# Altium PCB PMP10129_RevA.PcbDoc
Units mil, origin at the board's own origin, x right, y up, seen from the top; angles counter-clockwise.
Board outline 7300 x 1875 mil, 2 copper layers (Top Layer, Bottom Layer), stack 62 mil thick; 91 components, 49 nets, 201 pads, 18 vias.
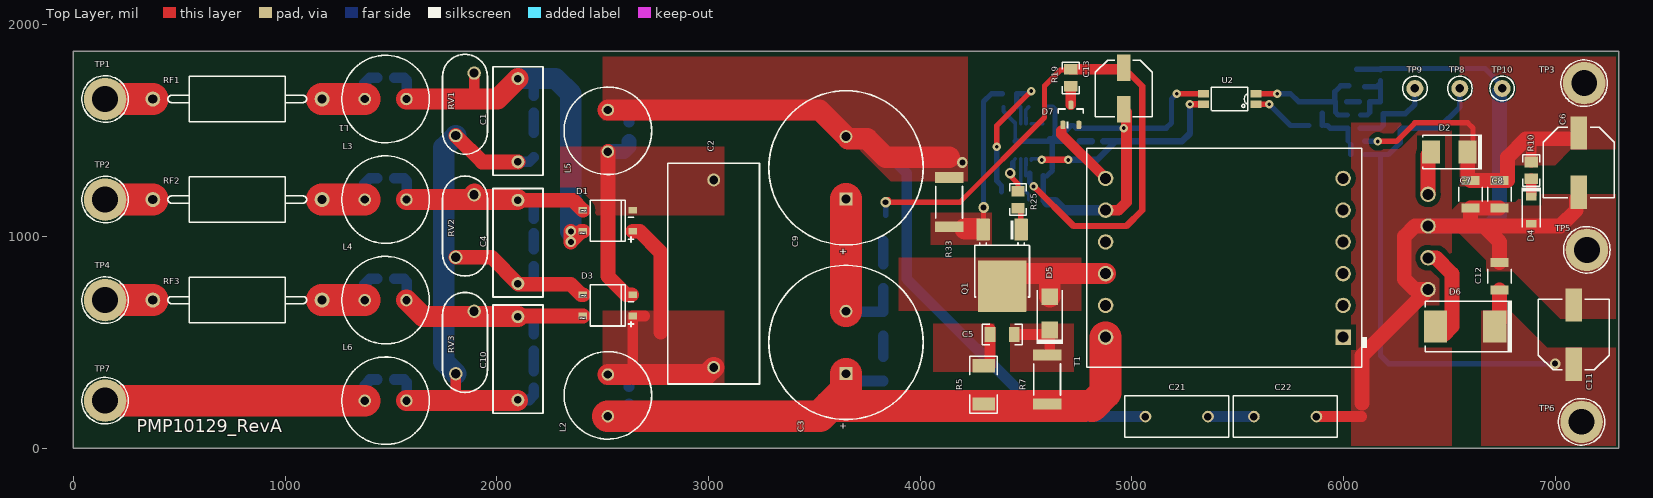
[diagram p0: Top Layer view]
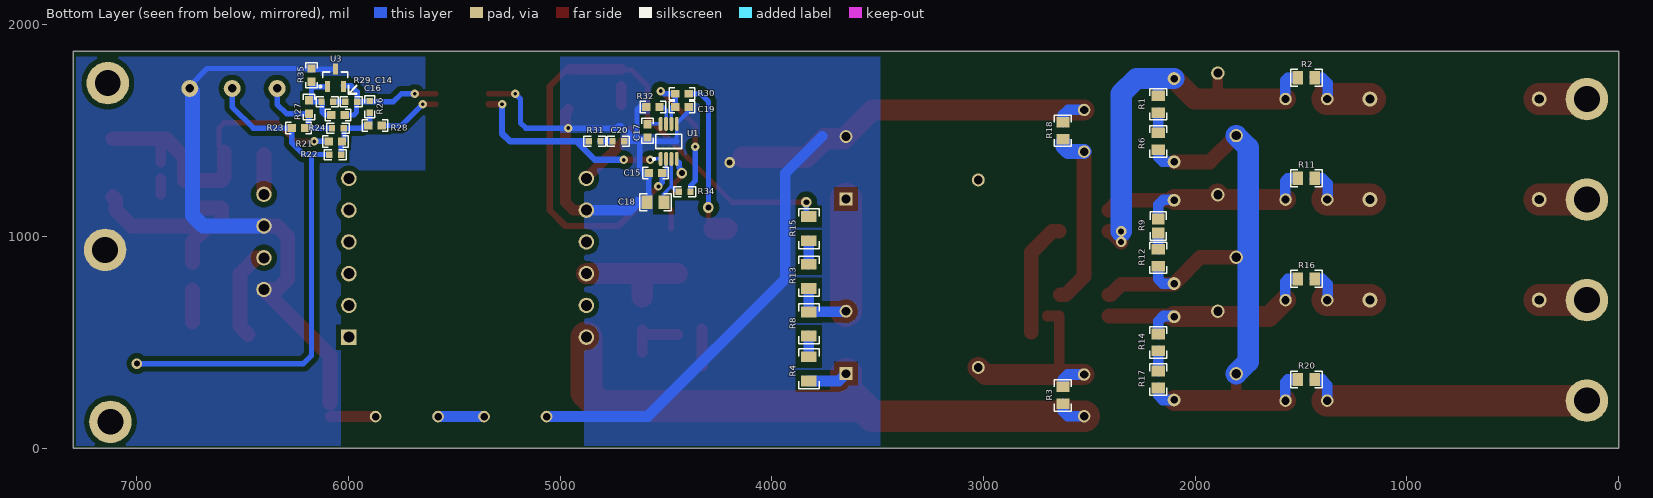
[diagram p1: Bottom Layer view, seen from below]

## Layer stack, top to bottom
Top Solder: solder mask 0.4, Solder Resist, Dk 3.5
Top Layer: signal copper 1.4
Dielectric1: core 59.2, FR-4, Dk 4.8
Bottom Layer: signal copper 1.4
Bottom Solder: solder mask 0.4, Solder Resist, Dk 3.5

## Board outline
0,0 7300,0 7300,1875 0,1875

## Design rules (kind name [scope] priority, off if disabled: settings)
AcuteAngle [All] p1: minimum=4.50000000000000E+0001 checktracksonly=FALSE
AssemblyTestPointUsage [All] p1: valid=2
Clearance Clearance_Keepouts [((IsTrack Or IsArc) And Not InPoly) And IsFree and IsKeepOut vs ((IsTrack Or IsArc) And Not InPoly) And IsFree and IsKeepOut] p1: gap=0
Clearance Clearance_BoardEdge_MountingHoles [OnCopper and InComponentClass('Mounting Holes') vs IsKeepOut] p2: gap=20
Clearance Clearance_BoardEdge_Poly [OnCopper and InPoly vs IsKeepOut] p3: gap=25
Clearance Clearance_BoardEdge [OnCopper and Not InComponentClass('Logo') and not InComponentClass('FiducialMark') and not InRegion(1000,500,4000,800) and Not IsKeepout vs IsKeepOut] p4: gap=20
Clearance Clearance_Poly [InPolygon] p5: gap=25
Clearance [All] p6: gap=7.87
ComponentClearance ComponentClearance_MountingHoles_FiducialMarks [InComponentClass('Mounting Holes') vs InComponentClass('FiducialMark')] p1: gap=50 collisioncheckmode=3 verticalgap=10 showdistances=FALSE
ComponentClearance ComponentClearance_Shunt [InComponentClass('Header') vs InComponentClass('Shunt')] p2: gap=0 collisioncheckmode=3 verticalgap=0 showdistances=FALSE
ComponentClearance ComponentClearance_Logo [InComponentClass('Logo')] p3: gap=50 collisioncheckmode=3 verticalgap=10 showdistances=FALSE
ComponentClearance ComponentClearance_ScrewToNut [(HasFootprint('NY PMS 440 0025 PH')) vs (HasFootprint('Keystone_1902C'))] p4: gap=5 collisioncheckmode=3 verticalgap=10 showdistances=FALSE
ComponentClearance ComponentClearance_MountingHoles [InComponentClass('Mounting Holes')] p5: gap=250 collisioncheckmode=3 verticalgap=100000 showdistances=FALSE
ComponentClearance ComponentClearance_SmallPassives [HasFootprint('0201*') or HasFootprint('0402*') or HasFootprint('0508') or HasFootprint('0603*') or HasFootprint('0612') or HasFootprint('0805*') or HasFootprint('0815*') or HasFootprint('0830*') or HasFootprint('1206*') or HasFootprint('1210*') or HasFootprint('1808*') or HasFootprint('1812*') or HasFootprint('1825*') or HasFootprint('2010*') or HasFootprint('2220*') or HasFootprint('2225*') or HasFootprint('2512*') or HasFootprint('2728*') or HasFootprint('3518*') vs HasFootprint('0201*') or HasFootprint('0402*') or HasFootprint('0508') or HasFootprint('0603*') or HasFootprint('0612') or HasFootprint('0805*') or HasFootprint('0815*') or HasFootprint('0830*') or HasFootprint('1206*') or HasFootprint('1210*') or HasFootprint('1808*') or HasFootprint('1812*') or HasFootprint('1825*') or HasFootprint('2010*') or HasFootprint('2220*') or HasFootprint('2225*') or HasFootprint('2512*') or HasFootprint('2728*') or HasFootprint('3518*')] p6: gap=20 collisioncheckmode=3 verticalgap=10 showdistances=FALSE
ComponentClearance ComponentClearance_THtoSMT [IsThruComponent vs IsSMTComponent] p7: gap=10 collisioncheckmode=3 verticalgap=10 showdistances=FALSE
ComponentClearance ComponentClearance_THtoTH [IsThruComponent vs IsThruComponent] p8: gap=20 collisioncheckmode=3 verticalgap=30 showdistances=FALSE
ComponentClearance [All] p9: gap=10 collisioncheckmode=3 verticalgap=10 showdistances=FALSE
DiffPairsRouting [All] p1: maxlimit=100 minlimit=10 mostfreqgap=10 toplayer_minwidth=15 toplayer_maxwidth=15 toplayer_prefwidth=15 bottomlayer_minwidth=15 bottomlayer_maxwidth=15 bottomlayer_prefwidth=15 maxuncoupledlength=1000
FabricationTestPointUsage TestPointUsage [All] p1: valid=2 allowmultiple=FALSE
FabricationTestpoint Testpoint [All] p1: side=3 testpointundercomponent=TRUE minsize=40 maxsize=100 preferedsize=60 minholesize=0 maxholesize=40 preferedholesize=32 testpointgrid=1 allowsidetop=TRUE allowsidebottom=TRUE usegrid=TRUE gridtolerance=0.01
FanoutControl Fanout_LCC [IsLCC] p1: bgadir=Out bgaviamode=Centered fanoutstyle=Auto fanoutdirection=Alternating viagrid=1 // Fanout_LCC (Default Rule)
FanoutControl Fanout_BGA [IsBGA] p2: bgadir=Out bgaviamode=Centered fanoutstyle=Auto fanoutdirection=Alternating viagrid=1 // Fanout_BGA (Default Rule)
FanoutControl Fanout_Default [All] p4: bgadir=Out bgaviamode=Centered fanoutstyle=Auto fanoutdirection=Alternating viagrid=1 // Fanout_Default (Default Rule)
FanoutControl Fanout_Small [(CompPinCount < 5)] p5: bgadir=Out bgaviamode=Centered fanoutstyle=Auto fanoutdirection=OutThenIn viagrid=1 // Fanout_Small (Default Rule)
Height [All] p1: minheight=0 maxheight=3000 prefheight=500
HoleSize [All] p1: absolutevalues=TRUE maxlimit=251 minlimit=8 maxpercent=80.000 minpercent=20.000
MinimumAnnularRing MinimumAnnularRing_ThermalPadVias [IsVia and InAnyComponent] p1: minimumring=5.91
MinimumAnnularRing [All] p2: minimumring=9
MinimumSolderMaskSliver MinimumSolderMaskSliver_Logo [InComponentClass('Logo') vs InComponentClass('Logo')] p1: minsoldermaskwidth=0.7
MinimumSolderMaskSliver [All] p2: minsoldermaskwidth=3.94
PlaneConnect [All] p1: planeconnectstyle=Relief reliefexpansion=10 reliefentries=4 reliefconductorwidth=10 reliefairgap=10
PolygonConnect [All] p1: connectstyle=Direct reliefconductorwidth=10 reliefentries=4 polygonreliefangle="90 Angle" airgapwidth=10
RoutingVias ThermalPadVias [IsVia and InAnyComponent] p1: holewidth=7.87 width=19.68 viastyle="Through Hole" minholewidth=7.87 minwidth=19.68 maxholewidth=12.99 maxwidth=23.62
RoutingVias [All] p2: holewidth=16 width=34 viastyle="Through Hole" minholewidth=7.87 minwidth=26 maxholewidth=40 maxwidth=65
SilkToBoardRegionClearance [Not ((IsComment or IsDesignator) And (Hide <> 'False')) and not InRegion(1000,500,4000,800)] p1:
SilkToSilkClearance SilkToSilkClearance_Pb-FreeLogo [(HasFootprint('Pb-Free_Overlay_Medium') OR HasFootprint('Pb-Free_Overlay_Small')) vs (HasFootprint('Pb-Free_Overlay_Medium') OR HasFootprint('Pb-Free_Overlay_Small'))] p1 off: silktosilkclearance=0
SilkToSilkClearance [All] p2 off: silktosilkclearance=5
SilkToSolderMaskClearance "Silk to Solder Mask Opening" [All] p1 off: minsilkscreentomaskgap=1 clearancetoexposedcopper=FALSE
SolderMaskExpansion [All] p1: expansion=1.97
UnpouredPolygon [All] p1: allowunpoured=FALSE
Width [All] p1: maxlimit=150 minlimit=6 preferedwidth=10 minimp=50.000000 maximp=50.000000 favimp=50.000000 checkconnectedcopper=TRUE
13 further rules are at their usual default settings.

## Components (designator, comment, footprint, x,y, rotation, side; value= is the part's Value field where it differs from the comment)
C1 "B32921C3104M" B32921_1300x1200x600 2100,1550 r270 top
C2 "B32653A224J" B32653_2650x2050x1100 3025,825 r90 top
C3 "EKXG401ELL680MM25S" KXG_1800x3150 3650,500 r90 top
C4 "B32921C3104M" B32921_1300x1200x600 2100,975 r270 top
C5 "C3216C0G2J152J" 1206 4387.5,537.5 r0 top
C6 "EEE-FK1H101P" SM_RADIAL_F 7112.5,1350 r270 top
C7 "C3225X7R1H106M250AC" 1210_280 6600,1200 r270 top
C8 "C3225X7R1H106M250AC" 1210_280 6737.5,1200 r270 top
C9 "EKXG401ELL680MM25S" KXG_1800x3150 3650,1325 r90 top
C10 "B32921C3104M" B32921_1300x1200x600 2100,425 r270 top
C11 "EEE-FK1A471P" SM_RADIAL_F 7087.5,537.5 r90 top
C12 "C3225X7R1C226K250AC" 1210_280 6737.5,812.5 r90 top
C13 "EEE-FC1H100P" SM_RADIAL_D 4962.5,1700 r270 top
C14 "Used in BOM report" 0603_HV 5987.5,1637.5 r180 bottom
C15 "C1608X7R1H104K" 0603 4550,1300 r0 bottom
C16 "C0603C103J5RACTU" 0603 6050,1575 r180 bottom
C17 "C1608X7R1H473K" 0603 4587.5,1500 r270 bottom
C18 "08055C105KAT2A" 0805_HV 4550,1162.5 r0 bottom
C19 "GRM1885C1H561JA01D" 0603 4425,1612.5 r180 bottom
C20 "Used in BOM report" 0603_HV 4725,1450 r180 bottom
C21 "VY2472M49Y5US63V7" VY2_1250x500x1650 5212.5,150 r0 top
C22 "VY2472M49Y5US63V7" VY2_1250x500x1650 5725,150 r0 top
D1 "MB8S-TP" MBS-1 2525,1075 r180 top
D2 "MURS140-13-F" SMB 6500,1400 r180 top
D3 "MB8S-TP" MBS-1 2525,675 r180 top
D4 "MMSZ5255B-7-F" SOD-123 6887.5,1125 r270 top
D5 "US1K-13-F" SMA 4612.5,637.5 r90 top
D6 "MBRS3100T3G" SMC 6575,575 r180 top
D7 "BAS21-7-F" SOT-23 4712.5,1575 r90 top
L1 "7447480102" WE_TI_1014 1475,1650 r0 top
L2 "7447480102" WE_TI_1014 2525,250 r270 top
L3 "7447480102" WE_TI_1014 1475,1175 r0 top
L4 "7447480102" WE_TI_1014 1475,700 r0 top
L5 "7447480102" WE_TI_1014 2525,1500 r90 top
L6 "7447480102" WE_TI_1014 1475,225 r0 top
Q1 "IPD90R1K2C3" DPAK 4387.5,900 r270 top
R1 "Used in BOM report" 0805_HV 2175,1625 r90 bottom
R2 "CRCW080510K0FKEA" 0805_HV 1475,1750 r0 bottom
R3 "CRCW080510K0FKEA" 0805_HV 2625,250 r270 bottom
R4 "CRCW1206499KFKEA" 1206 3825,375 r270 bottom
R5 "CRCW2010150RJNEF" 2010 4300,300 r270 top
R6 "Used in BOM report" 0805_HV 2175,1450 r90 bottom
R7 "CRCW251247K0JNEG" 2512 4600,325 r270 top
R8 "CRCW1206499KFKEA" 1206 3825,587.5 r270 bottom
R9 "Used in BOM report" 0805 2175,1050 r90 bottom
R10 "CRCW08050000Z0EAHP" 0805_HV 6887.5,1312.5 r90 top
R11 "CRCW080510K0FKEA" 0805_HV 1475,1275 r0 bottom
R12 "Used in BOM report" 0805_HV 2175,900 r90 bottom
R13 "CRCW1206499KFKEA" 1206 3825,812.5 r270 bottom
R14 "Used in BOM report" 0805_HV 2175,500 r90 bottom
R15 "CRCW1206499KFKEA" 1206 3825,1037.5 r270 bottom
R16 "CRCW080510K0FKEA" 0805_HV 1475,800 r0 bottom
R17 "Used in BOM report" 0805_HV 2175,325 r90 bottom
R18 "CRCW080510K0FKEA" 0805_HV 2625,1500 r90 bottom
R19 "CRCW080510R0FKEA" 0805_HV 4712.5,1750 r270 top
R20 "CRCW080510K0FKEA" 0805_HV 1475,325 r0 bottom
R21 "CRCW06030000Z0EA" 0603 6062.5,1450 r0 bottom
R22 "Used in BOM report" 0603_HV 6062.5,1387.5 r0 bottom
R23 "CRCW060349R9FKEA" 0603 6237.5,1512.5 r0 bottom
R24 "Used in BOM report" 0603_HV 6050,1512.5 r0 bottom
R25 "CRCW08050000Z0EA" 0805_HV 4462.5,1175 r270 top
R26 "Used in BOM report" 0603_HV 5900,1612.5 r270 bottom
R27 "CRCW060320K0FKEA" 0603 6187.5,1612.5 r270 bottom
R28 "CRCW06032K00JNEA" 0603 5875,1525 r0 bottom
R29 "Used in BOM report" 0603_HV 6100,1637.5 r0 bottom
R30 "RT0603DRE07499RL" 0603 4425,1675 r180 bottom
R31 "Used in BOM report" 0603_HV 4837.5,1450 r0 bottom
R32 "CRCW060360K4FKEA" 0603 4562.5,1612.5 r180 bottom
R33 "ERJ-1TRQFR62U" 2512 4137.5,1162.5 r270 top
R34 "Used in BOM report" 0603_HV 4412.5,1212.5 r0 bottom
R35 "CRCW06035K23FKEA" 0603 6175,1762.5 r270 bottom
RF1 "FW20A10R0JACT-ND" RES_PWR4522 775,1650 r180 top
RF2 "FW20A10R0JACT-ND" RES_PWR4522 775,1175 r180 top
RF3 "FW20A10R0JACT-ND" RES_PWR4522 775,700 r180 top
RV1 "S10K275E2" VAR_S10K275E2 1850,1625 r90 top
RV2 "S10K275E2" VAR_S10K275E2 1850,1050 r90 top
RV3 "S10K275E2" VAR_S10K275E2 1850,500 r90 top
T1 "750315315" Wurth_750315315 5437.5,900 r180 top
TP1 "Suggest using a net name here" Keystone1503-2 150,1650 r270 top
TP2 "Suggest using a net name here" Keystone1503-2 150,1175 r270 top
TP3 "Suggest using a net name here" Keystone1503-2 7137.5,1725 r0 top
TP4 "Suggest using a net name here" Keystone1503-2 150,700 r270 top
TP5 "Suggest using a net name here" Keystone1503-2 7150,937.5 r0 top
TP6 "Suggest using a net name here" Keystone1503-2 7125,125 r0 top
TP7 "Suggest using a net name here" Keystone1503-2 150,225 r270 top
TP8 "5000" Keystone5000 6550,1700 r0 top
TP9 "5000" Keystone5000 6337.5,1700 r0 top
TP10 "5001" Keystone5001 6750,1700 r0 top
U1 "LM5021MM-1/NOPB" MUA08A_N 4487.5,1450 r90 bottom
U2 "TCMT1107" SOP-4 5462.5,1650 r180 top
U3 "LMV431AIMF/NOPB" MF03A_N 6062.5,1750 r90 bottom

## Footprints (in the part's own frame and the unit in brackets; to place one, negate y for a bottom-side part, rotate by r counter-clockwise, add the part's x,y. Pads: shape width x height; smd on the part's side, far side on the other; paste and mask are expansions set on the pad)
0603 [mm] "0603 from SM-752 data"
  rect 1x0.95 smd: 1(-0.8,0) 2(0.8,0)
  silkscreen extent -1.52,-0.69 1.52,0.69, body extent -0.87,-0.47 0.87,0.47, height 0.85
0603_HV [mil] "Ernesto recommended land pattern.  26 mil between pads."
  rect 30x30 smd: 1(-28,0) 2(28,0)
  silkscreen extent -52,-24 52,24, body extent -34,-19 34,19, height 33
0805 [mm] "0805 from SM-752 data"
  rect 1.3x1.5 smd: 1(-0.85,0) 2(0.85,0)
  silkscreen extent -1.72,-0.97 1.72,0.97, body extent -1.1,-0.72 1.1,0.72, height 1.1
0805_HV [mil] "0805 with 30mil clearance between pads"
  rect 50x63 smd: 1(-40,0) 2(40,0)
  silkscreen extent -74,-40 74,40, body extent -43,-29 43,29, height 57
1206 [mm] "1206 from SM-752 data"
  rect 1.3x1.85 smd: 1(-1.45,0) 2(1.45,0)
  silkscreen extent -2.4,-1.21 2.4,1.21, body extent -1.7,-0.9 1.7,0.9, height 1.35
1210_280 [mm] "SMD, 2-Leads, Body 3.6x2.8mm, Height 2.8mm"
  rect 1.1x2.2 smd: 1(-1.65,0) 2(1.65,0)
  silkscreen extent -0.84,-1.4 0.84,1.4, body extent -1.8,-1.4 1.8,1.4, height 2.8
2010 [mm] "Chip Capacitor, Body 5.08x2.54mm, IPC Medium Density"
  rect 1.6x2.7 smd: 1(-2.3,0) 2(2.3,0)
  silkscreen extent -3.42,-1.65 3.42,1.65, body extent -2.73,-1.45 2.73,1.45, height 1.66
2512 [mm] "Chip Resistor, Body 6.3x3.2mm, IPC Medium Density"
  rect 1.3x3.4 smd: 1(-2.95,0) 2(2.95,0)
  silkscreen extent -1.9,-1.6 1.9,1.6, body extent -3.22,-1.67 3.22,1.67, height 0.71
B32653_2650x2050x1100 [mm] "TH, 2-Leads, Body 26.5x11mm, Pin Spacing 22.5mm"
  round 1.55 hole 1.05: 1(-11.25,0) 2(11.25,0)
  silkscreen extent -13.25,-5.5 13.25,5.5, body extent -13.25,-5.5 13.25,5.5, height 20.5
B32921_1300x1200x600 [mm] "EPCOS"
  round 1.55 hole 0.9: 1(-5,0) 2(5,0)
  silkscreen extent -6.4,-3 6.6,3, body extent -6.4,-3 6.6,3, height 12
DPAK [mm] "D-PAK, 3-Pads, Body 6.22x6.73mm (max), TO-252AA using nominal STEP model"
  rrect6% 2.6x1.6 smd: 1(-3.4,2.28) 3(-3.4,-2.28)
  rrect2% 6.2x5.8 smd paste-2.9: 4(3.4,0)
  silkscreen extent -4.5,-3.3 4.7,3.28, body extent -3.86,-3.29 5.84,3.29, height 2.48
Keystone1503-2 [mm] "Double Turret"
  round 5.1 hole 3.1: 1(0,0)
  silkscreen extent -2.79,-2.79 2.79,2.79, body extent -2.4,-2.4 2.38,2.4, height 9.22
Keystone5000 [mil] "For Keystone 500x miniature loop terminals"
  round 80 hole 40: 1(0,0)
  silkscreen extent -58,-58 58,58, body extent -49,-49 49,49, height 182
Keystone5001 [mil] "For Keystone 500x miniature loop terminals"
  round 80 hole 40: 1(0,0)
  silkscreen extent -58,-58 58,58, body extent -49,-49 49,49, height 182
KXG_1800x3150 [mm] "TH, 2-Leads, Dia 18mm, Pin Spacing 7.5mm"
  rect 1.55x1.55 hole 1.05: 1(-3.75,0)
  round 1.55 hole 1.05: 2(3.75,0)
  silkscreen extent -9.25,-9.25 9.25,9.25, body extent -9.18,-9.33 9.22,9.14, height 33.01
MBS-1 [mm] "SOP, 4-Leads, Body 4.95x4.2mm"
  rect 1x0.8 smd: 1(-3,1.27) 2(3,1.27) 3(3,-1.27) 4(-3,-1.27)
  silkscreen extent -3.08,-2.48 2.1,2.56, body extent -3.45,-2.47 3.45,2.48, height 2.9
MF03A_N [mm] "SOT23, 3-Leads, Body 2.9x1.3mm, Pitch 0.95mm, Lead Span 2.4mm, IPC Medium Density"
  rect 1.3x0.6 smd: 1(-1.05,0.95) 2(-1.05,-0.95) 3(1.05,0)
  silkscreen extent -1.17,-1.5 0.7,1.93, body extent -0.7,-1.5 0.7,1.5, height 1.12
MUA08A_N [mm] "TSOP, 8-Leads, Body 3x3mm, Pitch 0.65mm, IPC Medium Density"
  oval 1.7x0.45 smd: 1(-2.1,0.975) 2(-2.1,0.325) 3(-2.1,-0.325) 4(-2.1,-0.975) 5(2.1,-0.975) 6(2.1,-0.325) 7(2.1,0.325) 8(2.1,0.975)
  silkscreen extent -2.22,-1.55 0.85,1.88, body extent -1.6,-1.6 1.6,1.6, height 1.09
RES_PWR4522 [mm] "Bourns fusible resistor"
  round 1.8 hole 1.1: 1(-10.16,0) 2(10.16,0)
  silkscreen extent -8.3,-2.76 8.35,2.74, body extent -10.58,-2.74 10.58,2.74, height 5.49
SM_RADIAL_D [mm] "6.3 x 5.8mm:  Panasonic D"
  rect 3.2x1.6 smd: 1(-2.5,0) 2(2.5,0)
  silkscreen extent -3.4,-3.4 3.4,3.4, body extent -3.41,-3.41 3.41,3.41, height 6.1
SM_RADIAL_F [mm] "8 x 10.2mm:  Panasonic F"
  rect 4x2 smd: 1(-3.55,0) 2(3.55,0)
  silkscreen extent -4.25,-4.25 4.25,4.25, body extent -4.26,-4.26 4.26,4.26, height 10.5
SMA [mm] "Molded Diode, 2-Leads, Body 4.3x2.6mm, IPC Medium Density, based on OnSemi component dimensions and land pattern"
  rect 2x2 smd: 1(-2,0) 2(2,0)
  silkscreen extent -3.66,-1.57 2.79,1.57, body extent -2.6,-1.3 2.6,1.3, height 2.42
SMB [mil] "Molded Diode, 2-Leads, Body 5.4x3.6mm, IPC Medium Density, based on OnSemi component dimensions"
  rect 85x107.99 smd: 1(-87.01,0) 2(87.01,0)
  silkscreen extent -155,-82 125,82, body extent -106,-71 106,71, height 91
SMC [mil] "Molded Diode, 2-Leads, Body 6.9x5.8mm, IPC Medium Density, based on OnSemi component dimensions and land patterns"
  rect 110x150 smd: 1(-140.49,0) 2(140.49,0)
  silkscreen extent -221,-124 189,123, body extent -156,-116 156,116, height 91
SOD-123 [mm] "On Semi recommended land pattern"
  rect 0.915x1.22 smd: 1(-1.637,0) 2(1.637,0)
  silkscreen extent -2.74,-1.17 2.03,1.17, body extent -1.93,-0.9 1.93,0.9, height 1.35
SOP-4 [mm] "Vishay Half Pitch Mini-Flat Package"
  rect 1.3x0.9 smd: 1(-3.15,0.635) 2(-3.15,-0.635) 3(3.15,-0.635) 4(3.15,0.635)
  silkscreen extent -2.2,-1.41 2.2,1.39, body extent -3.5,-1.4 3.5,1.4, height 2.12
SOT-23 [mm] "SOT23, 3-Leads, Body 2.9x1.3mm, Pitch 0.95mm, Lead Span 2.5mm, IPC Medium Density"
  rrect50% 1x0.6 smd: 1(-1.2,0.95) 2(-1.2,-0.95) 3(1.2,0)
  silkscreen extent -1.63,-1.5 0.7,1.5, body extent -1.16,-1.45 1.21,1.45, height 1
VAR_S10K275E2 [mm] "EPCOS"
  round 1.6 hole 1.1: 1(-3.75,1.1) 2(3.75,-1.1)
  silkscreen extent -6,-2.7 6,2.7, body extent -5.98,-2.7 5.98,2.7, height 14.99
VY2_1250x500x1650 [mm] "TH, 2- Leads, Body 12.5x5mm, Pin Spacing 7.5mm"
  round 1.4 hole 0.9: 1(-3.75,0) 2(3.75,0)
  silkscreen extent -6.25,-2.5 6.25,2.5, body extent -6.2,-2.5 6.25,2.5, height 16.49
WE_TI_1014 [mm] "TH, 2-Leads, Dia 10.5mm, Pitch 1mm"
  round 1.5 hole 1: 1(-2.5,0) 2(2.5,0)
  silkscreen extent -5.25,-5.25 5.25,5.25, body extent -5.26,-5.26 5.26,5.26, height 14.5
Wurth_750315315 [mm] "TH, 12-Leads, Body 33x26.3mm, Pitch 3.81mm"
  rect 1.85x1.85 hole 1.32: 1(-14.25,9.525)
  round 1.85 hole 1.32: 2(-14.25,5.715) 3(-14.25,1.905) 4(-14.25,-1.905) 5(-14.25,-5.715) 6(-14.25,-9.525) 7(14.25,-9.525) 8(14.25,-5.715) 9(14.25,-1.905) 10(14.25,1.905) 11(14.25,5.715) 12(14.25,9.525) A(-24.447,-7.62) B(-24.447,-3.81) C(-24.447,0) D(-24.447,3.81)
  silkscreen extent -17.1,-13.15 16.5,13.15, body extent -18,-13.15 16.5,13.15, height 14.76

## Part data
C1 C4 C10: "CAP, Film, 0.1 µF, 305 V, +/- 20%, TH"
C2: "CAP, Film, 0.22 µF, 1000 V, +/- 5%, TH"
C3 C9: library part EKXG451ELL680MMN3S, "CAP, AL, 68 µF, 400 V, +/- 20%,  ohm, TH"
C5: "CAP, CERM, 1500 pF, 630 V, +/- 5%, C0G/NP0, 1206"
C6: "CAP, AL, 100 µF, 50 V, +/- 20%, 0.34 ohm, SMD"
C7 C8: "CAP, CERM, 10 µF, 50 V, +/- 20%, X7R, 1210"
C11: "CAP, AL, 470 µF, 10 V, +/- 20%, 0.16 ohm, SMD"
C12: "CAP, CERM, 22 µF, 16 V, +/- 10%, X7R, 1210"
C13: "CAP, AL, 10 µF, 50 V, +/- 20%, 2 ohm, SMD"
C14 C20: library part Capacitor, "CAP, CERM, xxxF, xxV, [TempCo], xx%, [PackageReference]"
C15: "CAP, CERM, 0.1 µF, 50 V, +/- 10%, X7R, 0603"
C16: "CAP, CERM, 0.01 µF, 50 V, +/- 5%, X7R, 0603"
C17: "CAP, CERM, 0.047 µF, 50 V, +/- 10%, X7R, 0603"
C18: "CAP, CERM, 1 µF, 50 V, +/- 10%, X7R, 0805"
C19: "CAP, CERM, 560 pF, 50 V, +/- 5%, C0G/NP0, 0603"
C21 C22: "CAP, CERM, 4700 pF, 440 V, +/- 20%, Y5U, TH, 12.5x5mm"
D1 D3: "Diode, Switching-Bridge, 800 V, 0.5 A, 4-Pin TO269AA, Body 4.95 x 4.2 mm, Pitch 2.555 mm"
D2: "Diode, Ultrafast, 400 V, 1 A, SMB"
D4: "Diode, Zener, 28 V, 500 mW, SOD-123"
D5: "Diode, Fast Rectifier, 800 V, 1 A, SMA"
D6: "Diode, Schottky, 100 V, 3 A, SMC"
D7: "Diode, Switching, 200 V, 0.2 A, SOT-23"
L1 L2 L3 L4 L5 L6: library part 7447480471, "Inductor, Wirewound, Ferrite, 470 µH, 1.15 A, 0.47 ohm, TH"
Q1: library part MOSFET_N_D4G1S3, "MOSFET, N-CH, xxV, xxxA, DPAK"
R1 R6 R9 R12 R14 R17 R22 R24 R26 R29 R31 R34: library part Resistor, "RES, xxx ohm, x%, xW, [PackageReference]"
R2 R3 R11 R16 R18 R20: "RES, 10.0 k, 1%, 0.125 W, 0805"
R4 R8 R13 R15: "RES, 499 k, 1%, 0.25 W, 1206"
R5: "RES, 150, 5%, 0.75 W, 2010"
R7: "RES, 47 k, 5%, 1 W, 2512"
R10: "RES, 0, 5%, 0.333 W, 0805"
R19: "RES, 10.0, 1%, 0.125 W, 0805"
R21: "RES, 0, 5%, 0.1 W, 0603"
R23: "RES, 49.9, 1%, 0.1 W, 0603"
R25: "RES, 0, 5%, 0.125 W, 0805"
R27: "RES, 20.0 k, 1%, 0.1 W, 0603"
R28: "RES, 2.0 k, 5%, 0.1 W, 0603"
R30: "RES, 499, 0.5%, 0.1 W, 0603"
R32: "RES, 60.4 k, 1%, 0.1 W, 0603"
R33: "RES, 0.62, 1%, 1 W, 2512"
R35: "RES, 5.23 k, 1%, 0.1 W, 0603"
RF1: library part PWR4522AS10R0JA, "RES, 10, 5%, 32W, Fusible, TH"
RF2 RF3: library part PWR4522AS10R0JA, "RES, 10, 5%, 2 W, Fusible, TH"
RV1 RV2 RV3: "Varistor 275V RMS 10MM Radial, TH"
T1: "Transformer, 400 uH, TH"
TP1 TP2 TP3 TP4 TP5 TP6 TP7: library part 1503-2, "Terminal, Turret, TH, Double"
TP8 TP9: "Test Point, Miniature, Red, TH"
TP10: "Test Point, Miniature, Black, TH"
U1: "AC-DC Current Mode PWM Controller, 8-pin MSOP, Pb-Free"
U2: "Optocoupler, 3.75kV RMS, SMT"
U3: "Low-Voltage (1.24V) Adjustable Precision Shunt Regulators, 3-pin SOT-23, Pb-Free"

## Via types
v1: diameter 40, hole 18, Top Layer to Bottom Layer, 11 vias
v2: diameter 50, hole 28, Top Layer to Bottom Layer, 7 vias

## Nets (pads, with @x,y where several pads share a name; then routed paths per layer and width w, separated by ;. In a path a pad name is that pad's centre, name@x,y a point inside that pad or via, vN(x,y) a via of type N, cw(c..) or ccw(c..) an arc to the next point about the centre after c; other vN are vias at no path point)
GND: C6.2 C7.2 C8.2 C11.2 C12.2 C22.2 D4.2 R35.1 T1.B T1.D TP5.1 TP10.1 U3.3 | length 4239.3
  Top Layer w50: C22.2@5875,150 6087.5,150
  Top Layer w70: 6087.5,212.5 6087.5,437.5 T1.D 6337.5,750 6287.5,800 6287.5,1000 6337.5,1050 T1.B 6600,1050 ; C12.2 6737.5,975 6662.5,1050 ; C8.2 C7.2 6600,1050 ; C6.2@7112.5,1187.5 7100,1175 7100,1125 7025,1050 6662.5,1050 ; 6600,1050 6662.5,1050
  Bottom Layer w25: U3.3 6171.16,1791.34 R35.1@6175,1787.5 ; R35.1 6668.5,1794 TP10.1@6750,1712.5
  Bottom Layer w70: T1.B 6687.5,1050 6737.5,1100 TP10.1@6737.5,1687.5
NetC1_1: C1.1 D1.2 L1.2 R1.2 R2.2 RV1.2 | length 1985.8
  Top Layer w50: 1893.31,1656.69 RV1.2
  Top Layer w70: v2(2350,1025) v2(2350,975) 2400,1025 D1.2
  Top Layer w100: L1.2 2003.15,1650 C1.1
  Bottom Layer w50: R2.2 1562.5,1750 1575,1737.5 L1.2@1575,1651.57 ; L1.2 L1.2@1575,1651.57 ; L1.2@1575,1650 L1.2@1575,1651.57 ; 2153.15,1746.85 2175,1725 R1.2
  Bottom Layer w100: C1.1 2153.15,1746.85 2278.15,1746.85 2350,1675 v2(2350,1025)
NetC1_2: C1.2 C4.2 C10.2 D3.3 L6.2 R6.1 R12.1 R17.1 R20.2 RV1.1 RV2.1 RV3.1 | length 3390.9
  Top Layer w50: 1806.69,231.69 RV3.1
  Top Layer w70: RV2.1 1975.79,902.36 C4.2 2103.15,775 2350,775 2400,725 D3.3 ; RV1.1 1930.91,1353.15 C1.2
  Top Layer w100: L6.2 C10.2@2096.85,225
  Bottom Layer w50: R20.2 1562.5,325 1575,312.5 L6.2@1575,226.57 ; L6.2 L6.2@1575,226.57 ; L6.2@1575,225 L6.2@1575,226.57 ; 1752.36,902.36 RV2.1 ; C10.2 2153.15,228.15 2175,250 R17.1 ; C4.2 2153.15,778.15 2175,800 R12.1 ; C1.2 2153.15,1353.15 2175,1375
  Bottom Layer w100: RV3.1 1750,409.06 1750,1420.67 RV1.1
NetC2_1: C2.1 D1.1 D3.1 L2.1 R3.1 | length 1518.3
  Top Layer w50: 2650,348.43 2643.11,355.32 D3.1 2700,625
  Top Layer w70: D1.1 2675,1025 2775,925 2775,550
  Top Layer w100: L2.1 2625,348.43 ; 2650,348.43 2991.34,348.43 C2.1
  Bottom Layer w50: L2.1 2601.57,348.43 2625,325 R3.1
NetC2_2: C2.2 D1.4 D3.4 L5.1 R18.1 | length 872.5
  Top Layer w70: L5.1 2525,812.5 2612.5,725 D3.4@2637.5,725
  Bottom Layer w70: L5.1 2601.57,1401.57 2625,1425 R18.1@2625,1450
NetC3_1: C3.1 L2.2 R3.2 R4.2 R5.2 R7.2 T1.12 | length 3139
  Top Layer w150: L2.2 3526.57,151.57 3575,200 ; C3.1 3650,275 3575,200 ; 4775,200 3575,200 ; 4812.5,200 4876.48,263.98 T1.12
  Bottom Layer w50: L2.2 2601.57,151.57 2625,175 R3.2 ; C3.1 3684.45,317.91 R4.2
NetC3_2: C3.2 C9.1 R8.1 R13.2 | length 816.8
  Top Layer w150: C3.2 C9.1
  Bottom Layer w50: C3.2 3653.05,644.59 R8.1 R13.2
NetC4_1: C4.1 D1.3 L3.2 R9.2 R11.2 RV2.2 | length 1154.3
  Top Layer w70: C4.1 2360.04,1171.85 D1.3
  Top Layer w100: L3.2 RV2.2@1893.31,1175 ; RV2.2 RV2.2@1895.67,1200 ; RV2.2@1895.67,1175 C4.1@2096.85,1175
  Bottom Layer w50: R11.2 1562.5,1275 1575,1262.5 L3.2@1575,1176.57 ; L3.2 L3.2@1575,1176.57 ; L3.2@1575,1175 L3.2@1575,1176.57 ; C4.1@2103.15,1175 2150,1175 2175,1150 R9.2
NetC5_1: C5.1 R5.1 | length 177.4
  Top Layer w50: R5.1@4330.41,387.5 C5.1@4330.41,564.86
NetC5_2: C5.2 D5.1 R7.1 | length 281.8
  Top Layer w50: C5.2 4591.24,537.5 D5.1 R7.1@4612.5,453.64
NetC6_1: C6.1 C7.1 C8.1 D2.1 R10.2 R21.2 TP3.1 | length 1543.8
  Top Layer w25: v1(6162.5,1450) 6250,1450 6337.5,1537.5 6587.5,1537.5 6612.5,1512.5 D2.1@6612.5,1425
  Top Layer w50: R10.2 6887.5,1450
  Top Layer w70: D2.1 6587.01,1277.95 C7.1 C8.1 6775.77,1264.96 6775.77,1375.77 6862.5,1462.5 C6.1@7112.5,1462.5
  Bottom Layer w25: R21.2@6100,1450 v1(6162.5,1450)
NetC10_1: C10.1 D3.2 L4.2 R14.2 R16.2 RV3.2 | length 1168.7
  Top Layer w70: C10.1 2103.15,625 D3.2
  Top Layer w100: L4.2 1651.57,621.85 C10.1
  Bottom Layer w50: R16.2 1562.5,800 1575,787.5 L4.2@1575,701.57 ; L4.2 L4.2@1575,701.57 ; L4.2@1575,700 L4.2@1575,701.57 ; C10.1 2103.15,625 2150,625 2175,600 R14.2
NetC11_1: C11.1 C12.1 D6.1 R22.2 R23.2 TP6.1 TP8.1 | length 2611.9
  Top Layer w70: D6.1@6737.5,597.01 C12.1
  Bottom Layer w25: R22.2@6100,1387.5 6175,1387.5 ; TP8.1 6550,1612.5 6450,1512.5 R23.2 6269,1444 6212.5,1387.5 6175,1387.5 ; v2(7000,400) 6212.5,400 6175,437.5 6175,1387.5
NetC13_1: C13.1 C15.1 R15.1 R19.1 U1.2 | length 3037.5
  Top Layer w25: v2@3850,1175 v2(3837.5,1162.5) 4187.5,1162.5 4587.5,1562.5 4587.5,1712.5 4662.5,1787.5 4710,1787.5 R19.1
  Top Layer w30: v1@4537.5,1237.5 4725,1050 4975,1050 5050,1125 5050,1710.93 C13.1 C13.1@4954.07,1790
  Top Layer w50: R19.1 C13.1@4954.07,1790
  Bottom Layer w17: C15.1@4500,1287.5 4500,1287.57 4500.05,1300.07 U1.2
  Bottom Layer w25: R15.1@3837.5,1100 v2(3837.5,1162.5) ; C15.1 4518.5,1256.5 v1@4537.5,1237.5
  other v1: 4536.12,1237.5
NetC14_1: C14.1 R29.1 | length 59.5
  Bottom Layer w25: C14.1 R29.1 R29.1@6075,1637.5
NetC14_2: C14.2 C16.2 R26.1 U2.2 U3.2 | length 622.8
  Top Layer w25: U2.2@5587.5,1675 v1(5687.5,1675)
  Bottom Layer w25: v1(5687.5,1675) 5750,1675 5787.5,1637.5 C14.2 5959.5,1684.5 5987.5,1712.5 U3.2@6025,1712.5 ; C14.2@5962.5,1637.5 5962.5,1587.5 5975,1575 C16.2
NetC16_1: C16.1 R27.1 R29.2 R35.2 U3.1 | length 322.1
  Bottom Layer w25: C16.1 6112.5,1575 6125,1587.5 R29.2@6125,1637.5 ; U3.1 6158.66,1708.66 ; R29.2 6175,1637.5 R35.2@6175,1725 ; R35.2@6162.5,1712.5 R35.2@6175,1725 ; R35.2@6175,1737.5 R35.2 R35.2@6175,1725
NetC17_1: C17.1 U1.8 | length 53.9
  Bottom Layer w17: U1.8 C17.1@4579.82,1532.68
NetC18_1: C18.1 R34.2 U1.3 | length 252.8
  Bottom Layer w17: R34.2 4450,1212.5 4475,1237.5 ; U1.3 4474.7,1237.8 4475,1237.5 ; C18.1@4512.5,1175 4512.5,1200 4475,1237.5
NetC19_1: C19.1 R30.1 R34.1 U1.6 | length 761.1
  Top Layer w25: v1(4362.5,1425) 4362.5,1525 v1(4525,1687.5)
  Bottom Layer w17: U1.6 C19.1@4474.7,1612.2
  Bottom Layer w25: v1(4362.5,1425) 4362.5,1262.5 4384.5,1240.5 R34.1 ; C19.1 R30.1@4456.5,1669 ; R30.1 4512.5,1675 v1(4525,1687.5)
NetC20_1: C20.1 R31.1 | length 59.5
  Bottom Layer w30: C20.1 R31.1 R31.1@4812.5,1450
NetC21_2: C21.2 C22.1 | length 214.9
  Bottom Layer w50: C21.2@5362.5,150 C22.1
NetD2_2: D2.2 T1.A | length 187
  Top Layer w70: T1.A D2.2@6400,1387.01
NetD4_1: D4.1 R10.1 | length 72.5
  Top Layer w50: D4.1@6887.5,1200 R10.1
NetD5_2: D5.2 Q1.4 T1.10 | length 538.9
  Top Layer w100: Q1.4@4446.36,825 4612.5,825 ; D5.2 4612.5,825 ; T1.10 4612.5,825
NetD6_2: D6.2 T1.C | length 446.6
  Top Layer w70: T1.C 6437.5,900 6512.5,825 6512.5,575 D6.2@6475,537.5
NetD7_1: D7.1 T1.7 | length 311.7
  Top Layer w50: 4667.21,1500 4667.21,1484.27 T1.7
NetD7_3: D7.3 R19.2 | length 87.8
  Top Layer w50: D7.3 R19.2
NetL1_1: L1.1 R2.1 RF1.1 | length 347.6
  Top Layer w150: RF1.1 L1.1
  Bottom Layer w50: L1.1 1375,1651.57 1375,1725 1400,1750 R2.1
NetL3_1: L3.1 R11.1 RF2.1 | length 347.6
  Top Layer w150: RF2.1 L3.1
  Bottom Layer w50: L3.1 1375,1176.57 1375,1250 1400,1275 R11.1
NetL4_1: L4.1 R16.1 RF3.1 | length 347.6
  Top Layer w150: RF3.1 L4.1
  Bottom Layer w50: L4.1 1375,701.57 1375,775 1400,800 R16.1
NetL6_1: L6.1 R20.1 TP7.1 | length 1370.7
  Top Layer w150: TP7.1 L6.1
  Bottom Layer w50: L6.1 1376.57,298.43 1401,322.85 1401,325 R20.1
NetQ1_1: Q1.1 R25.2 | length 87.5
  Top Layer w25: Q1.1@4475,1037.5 R25.2@4475,1125
NetQ1_3: Q1.3 R30.2 R33.2 | length 800.8
  Top Layer w25: R33.2@4175,1050 4237.5,1050 ; Q1.3@4300,1062.5 v2(4300,1137.5)
  Top Layer w100: 4212.5,1037.5 Q1.3@4272.74,1037.5
  Bottom Layer w25: v2(4300,1137.5) 4300,1637.5 4337.5,1675 R30.2@4387.5,1675
NetR1_1: R1.1 R6.2 | length 95
  Bottom Layer w50: R6.2 R1.1
NetR4_1: R4.1 R8.2 | length 98.3
  Bottom Layer w50: R4.1 R8.2
NetR9_1: R9.1 R12.2 | length 76.5
  Bottom Layer w50: R12.2 R9.1
NetR13_1: R13.1 R15.2 | length 110.8
  Bottom Layer w50: R13.1 R15.2
NetR14_1: R14.1 R17.2 | length 95
  Bottom Layer w50: R17.2 R14.1
NetR21_1: R21.1 R22.1 R24.1 R26.2 R28.2 | length 280.7
  Bottom Layer w25: R28.2@5900,1525 R26.2 ; R28.2@5912.5,1525 5925,1525 5937.5,1512.5 R24.1 R21.1@6022,1453 ; R22.1 R21.1@6034.5,1434.5
NetR23_1: R23.1 R24.2 R27.2 TP9.1 | length 407.9
  Bottom Layer w25: R24.2 6175,1512.5 6187.5,1525 R27.2@6187.5,1575 ; R27.2 6293.5,1581 6337.5,1625 TP9.1
NetR25_1: R25.1 U1.4 | length 189.4
  Top Layer w25: v2@4412.5,1300 4462.5,1250 R25.1 R25.1@4462.5,1212.5
  Bottom Layer w17: 4437.5,1350 U1.4
  Bottom Layer w25: v2@4412.5,1300 4437.5,1325 4437.5,1350
  other v2: 4425,1300
NetR28_1: R28.1 U2.1 | length 291.4
  Top Layer w25: U2.1@5587.5,1625 v1(5650,1625)
  Bottom Layer w25: v1(5650,1625) 5750,1525 R28.1@5837.5,1525
NetR31_2: R31.2 U1.1 U2.4 | length 1055.6
  Top Layer w30: v1(4575,1362.5) v1(4700,1362.5) ; v1(5275,1625) U2.4@5337.5,1625
  Bottom Layer w17: U1.1@4525.89,1361.61 U1.1 4557.68,1367.32 v1@4562.5,1362.5
  Bottom Layer w30: v1(4700,1362.5) 4837.5,1362.5 4925,1450 ; R31.2 4925,1450 ; v1(5275,1625) 5275,1487.5 5237.5,1450 4925,1450
NetR32_2: R32.2 U1.7 | length 85
  Bottom Layer w17: U1.7 4500,1600 R32.2@4512.5,1612.5
NetRF1_2: RF1.2 TP1.1 | length 225
  Top Layer w150: TP1.1 RF1.2
NetRF2_2: RF2.2 TP2.1 | length 225
  Top Layer w150: TP2.1 RF2.2
NetRF3_2: RF3.2 TP4.1 | length 225
  Top Layer w150: TP4.1 RF3.2
PGND: C9.2 C13.2 C15.2 C17.2 C18.2 C19.2 C20.2 C21.1 L5.2 R18.2 R32.1 R33.1 T1.8 U1.5 U2.3 | length 6637
  Top Layer w25: v1(5212.5,1675) U2.3
  Top Layer w50: T1.8@4875,1125 T1.8 4937.5,1125 4975,1162.5 4975,1587.5 4962.5,1600 C13.2
  Top Layer w100: L5.2 3524.21,1598.43 C9.2 3660.14,1462.5 3750,1462.5 3837.5,1375 4137.5,1375
  Bottom Layer w17: U1.5 4449.11,1463.39 4456.25,1456.25
  Bottom Layer w20: C19.2 4393.5,1591.97 U1.5@4447.97,1537.5
  Bottom Layer w25: 4450,1450 4612.5,1450 ; C18.2@4581.5,1168.5 C15.2@4581.5,1287.5 ; R32.1 4625,1612.5 4637.5,1600 4637.5,1475 4625,1462.5 4612.5,1462.5 4612.5,1450 ; C15.2@4600,1287.5 4625,1312.5 ; 4625,1325 4625,1450 ; C20.2 4637.5,1450 ; v1(5212.5,1675) 5187.5,1650 5187.5,1537.5 5162.5,1512.5 4737.5,1512.5 4725,1525 4712.5,1525 4637.5,1450 ; 4612.5,1450 4637.5,1450
  Bottom Layer w50: L5.2 2526.57,1600 2600,1600 2625,1575 R18.2 ; 3762.5,1475 3937.5,1300 3937.5,800 4587.5,150 C21.1 ; C18.2@4600,1162.5 4637.5,1162.5 4675,1125 T1.8
  other v1: 4962.5,1512.5
  other v2: 4200,1350
pads on no net: D7.2 T1.1 T1.2 T1.3 T1.4 T1.5 T1.6 T1.9 T1.11

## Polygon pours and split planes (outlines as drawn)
NetC5_1 on Top Layer "Top Layer-No Net 10" (solid, remove dead copper, pour order 27): 4062.5,587.5 4350,587.5 4350,362.5 4062.5,362.5
GND on Top Layer "Top Layer-No Net 9" (solid, remove dead copper, pour order 24): 6037.5,1537.5 6512.5,1537.5 6512.5,12.5 6037.5,12.5
NetC11_1 on Top Layer "Top Layer-No Net 5" (solid, remove dead copper, pour order 20): 6650,650 6787.5,650 6962.5,475 7000,475 7287.5,475 7287.5,12.5 6650,12.5
GND on Top Layer "Top Layer-No Net 4" (solid, remove dead copper, pour order 19): 6425,1087.5 6475,1087.5 6550,1162.5 6800,1162.5 6812.5,1162.5 6862.5,1212.5 6875,1200 7287.5,1200 7287.5,600 7275,612.5 7050,612.5 7025,612.5 6800,837.5 6675,837.5 6675,887.5 6550,1012.5 6537.5,1025 6425,1025
NetC6_1 on Top Layer "Top Layer-No Net 3" (solid, remove dead copper, pour order 18): 6550,1237.5 6550,1850 7287.5,1850 7287.5,1412.5 7075,1412.5 7000,1337.5 6987.5,1337.5 6787.5,1337.5 6787.5,1237.5
NetC2_2 on Top Layer "Top Layer-No Net" (solid, remove dead copper, pour order 15): 2300,1425 2300,1150 2411.42,1150 2425,1136.42 2450,1111.42 2450,1100 3075,1100 3075,1425
NetC2_1 on Top Layer "Top Layer-No Net 1" (solid, remove dead copper, pour order 16): 2500,650 3075,650 3075,303.35 2503.35,303.35 2500,300
PGND on Top Layer "Top Layer-No Net 2" (solid, remove dead copper, pour order 17): 2500,1850 2500,1550 3575,1550 3862.5,1262.5 4225,1262.5 4225,1850
NetD5_2 on Top Layer "Top Layer-No Net 6" (solid, remove dead copper, pour order 21): 4762.5,650 3900,650 3900,900 4762.5,900
NetC5_2 on Top Layer "Top Layer-No Net 7" (solid, remove dead copper, pour order 23): 4425,587.5 4725,587.5 4725,362.5 4425,362.5
NetQ1_3 on Top Layer "Top Layer-No Net 8" (solid, remove dead copper, pour order 25): 4050,1112.5 4337.5,1112.5 4337.5,962.5 4050,962.5
PGND on Bottom Layer "Bottom Layer-No Net 2" (solid, remove dead copper, pour order 28): 4850,1850 5000,1850 5000,1487.5 4850,1487.5
PGND on Bottom Layer "Bottom Layer-No Net 1" (solid, remove dead copper, pour order 26): 3487.5,1850 4887.5,1850 4887.5,12.5 3487.5,12.5
GND on Bottom Layer "Bottom Layer-No Net" (solid, remove dead copper, pour order 22): 5637.5,1850 7287.5,1850 7287.5,12.5 6037.5,12.5 6037.5,1300 6025,1312.5 5637.5,1312.5

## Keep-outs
Keep-Out Layer:
  text ".Layer_Name" at 577,-858.49 h60

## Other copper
Top Layer:
  text ".Layer_Name" at 577,-858.49 h60
Bottom Layer:
  text ".Layer_Name" at 577,-858.49 h60

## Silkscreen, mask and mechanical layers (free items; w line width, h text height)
Top Overlay:
  text "PMP10129_RevA" at 300,75 h60
  text ".Layer_Name" at 577,-858.49 h30
Bottom Overlay:
  lines w10: 5962.5,1675 6000,1675 ; 5962.5,1712.5 6000,1675 ; 6000,1712.5 6000,1675
  text ".Layer_Name" at 577,-858.49 h30
Top Paste:
  text ".Layer_Name" at 577,-858.49 h60
Bottom Paste:
  text ".Layer_Name" at 577,-858.49 h60
Top Solder:
  text ".Layer_Name" at 577,-858.49 h60
  text ".Layer_Name" at 577,-858.49 h60
Bottom Solder:
  text ".Layer_Name" at 577,-858.49 h60
Drill Guide:
  text ".Layer_Name" at 577,-858.49 h60
M1 Board Outline:
  the board outline again, w10
  text ".Layer_Name" at 577,-858.49 h60
M2 Board Dimensions:
  rectangle: 125,-400 500,-275
  rectangle: 0,-275 125,-150
  lines w7: 0,-275 1000,-275 ; 125,-400 125,-150 ; 250,-400 250,-150 ; 500,-400 500,-150 ; 750,-400 750,-150 ; 0,-400 0,-150 1000,-150 1000,-400 0,-400
  text ".Layer_Name" at 577,-858.49 h60
M3 3D STEP Top:
  text ".Layer_Name" at 577,-858.49 h60
M4 3D STEP Bottom:
  text ".Layer_Name" at 577,-858.49 h60
M5 Assembly Top:
  lines w10: -292,-930.17 6308,-930.17 ; -292,-726.83 6310,-726.83 ; -292,-523.5 -292,-1133.5 3713,-1133.5 6310,-1133.5 6310,-523.5 -291.5,-523.5 -291.5,-1133.5 1284,-1133.5 ; 2173,-1133.5 2173,-523.5 ; 3440,-726.83 3440,-523.5 ; 4280,-726.83 4280,-523.5 ; 4902,-1140 4902,-937.17
  text "PCB VIEWED FROM TOP SIDE" at -228.5,-655.67 h60
  text "BOARD #:" at 2248,-655.67 h60
  text ".PRJ_Number" at 2793.5,-655.67 h60
  text "REV:" at 3638,-655.67 h60
  text ".PCB_Rev" at 3929.5,-655.67 h60
  text "SVN REV:" at 4476,-655.67 h60
  text ".VersionControl_RevNumber" at 4982,-655.67 h60
  text "PLOT NAME =" at -228.5,-1064.34 h60
  text ".plot_File_Name" at 577,-1064.34 h60
  text "GENERATED    :" at 2250,-1064.34 h60
  text ".Print_Date" at 3119.5,-1064.34 h60
  text ".Print_Time" at 3848.5,-1064.34 h60
  text "TEXAS INSTRUMENTS" at 5113,-1064.34 h60
M6 Assembly Bottom:
  lines w10: -292.5,-727.33 6309.5,-727.33 ; -290.5,-930.67 6309.5,-930.67 ; 1115.5,-1140.5 1115.5,-937.67 ; 1737.5,-727.33 1737.5,-524 ; 2577.5,-727.33 2577.5,-524 ; 3844.5,-1134 3844.5,-524 ; 4733.5,-1134 6309,-1134 6309,-524 -292.5,-524 -292.5,-1134 2304.5,-1134 6309.5,-1134 6309.5,-524
  text ".VersionControl_RevNumber" at 1035.5,-656.17 h60
  text "SVN REV:" at 1541.5,-656.17 h60
  text ".PCB_Rev" at 2088,-656.17 h60
  text "REV:" at 2379.5,-656.17 h60
  text ".PRJ_Number" at 3224,-656.17 h60
  text "BOARD #:" at 3769.5,-656.17 h60
  text "PCB VIEWED FROM BOTTOM SIDE" at 6246,-656.17 h60
  text "TEXAS INSTRUMENTS" at 904.5,-1064.84 h60
  text ".Print_Time" at 2169,-1064.84 h60
  text ".Print_Date" at 2898,-1064.84 h60
  text "GENERATED    :" at 3767.5,-1064.84 h60
  text ".plot_File_Name" at 5440.5,-1064.84 h60
  text "PLOT NAME =" at 6246,-1064.84 h60
M9 Title Sheet:
  drawing of 57 lines, arcs and shapes, not listed
  text "1" at 739.84,8036.5 h70
  text "2" at 3235.5,8036.5 h70
  text "3" at 5724.84,8036.5 h70
  text "4" at 8231.51,8036.5 h70
  text "5" at 10730.5,8036.5 h70
  text "6" at 13235.5,8036.5 h70
  text "A" at -416.5,6893.5 h70
  text "A" at 14383.5,6893.5 h70
  text "B" at -416.5,4513.5 h70
  text "B" at 14383.5,4513.5 h70
  text "C" at -416.5,2138.5 h70
  text "C" at 14383.5,2138.5 h70
  text "PROJECT TITLE:" at 11343.5,277.5 h45
  text ".PRJ_Title" at 11393.5,144.17 h70
  text "DESIGNED FOR:" at 11343.5,-23.5 h45
  text ".PRJ_Customer" at 11393.5,-163.5 h70
  text "D" at -416.5,-231.5 h70
  text "D" at 14383.5,-231.5 h70
  text "FILE NAME:" at 11343.5,-323.5 h45
  text ".PCB_File_Name_No_Path" at 11393.5,-443.5 h70
  text "Texas Instruments (TI) and/or its licensors do not warrant the accuracy or completeness of this specification" at 6374,-605.34 h45
  text "ENGINEER:" at 11343.5,-613.5 h45
  text "LAYOUT BY:" at 12848.5,-613.5 h45
  text "or any information contained therein. TI and/or its licensors do not warrant that this design will meet" at 6329.01,-718 h45
  text ".PRJ_Engineer" at 11393.5,-768.49 h70
  text ".PCB_Layout" at 12899,-768.49 h70
  text "the specifications, will be suitable for your application or fit for any particular purpose, or will operate in" at 6329.01,-830.67 h45
  text ".Layer_Name" at 577,-858.49 h60
  text "ALTIUM DESIGNER VERSION:" at 12848.5,-923.5 h45
  text "an implementation. TI and/or its licensors do not warrant that the design is production worthy. You should" at 6329.01,-943.33 h45
  text "completely validate and test your design implementation to confirm the system functionality for your application." at 6374,-1056 h45
  text ".print_Scale" at 11393.5,-1056.83 h70
  text ".Application_BuildNumber" at 12899,-1056.83 h70
  text "1" at 739.84,-1263.5 h70
  text "2" at 3235.5,-1263.5 h70
  text "3" at 5724.84,-1263.5 h70
  text "4" at 8231.51,-1263.5 h70
  text "5" at 10730.5,-1263.5 h70
  text "6" at 13235.5,-1263.5 h70
M10 Fab Notes:
  text ".Layer_Name" at 577,-858.49 h60
M11 Gerber Information:
  lines w10: -292,-930.17 6308,-930.17 ; -292,-726.83 6310,-726.83 ; -292,-523.5 -292,-1133.5 3713,-1133.5 6310,-1133.5 6310,-523.5 -291.5,-523.5 -291.5,-1133.5 1284,-1133.5 ; 2173,-1133.5 2173,-523.5 ; 3440,-726.83 3440,-523.5 ; 4280,-726.83 4280,-523.5 ; 4902,-1140 4902,-937.17
  text "ALL ARTWORK VIEWED FROM TOP SIDE" at -228.5,-655.67 h60
  text "BOARD #:" at 2248,-655.67 h60
  text ".PRJ_Number" at 2793.5,-655.67 h60
  text "REV:" at 3638,-655.67 h60
  text ".PCB_Rev" at 3929.5,-655.67 h60
  text "SVN REV:" at 4476,-655.67 h60
  text ".VersionControl_RevNumber" at 4982,-655.67 h60
  text "LAYER NAME =" at -228.5,-858.49 h60
  text "PLOT NAME =" at -228.5,-1064.34 h60
  text ".plot_File_Name" at 577,-1064.34 h60
  text "GENERATED    :" at 2250,-1064.34 h60
  text ".Print_Date" at 3119.5,-1064.34 h60
  text ".Print_Time" at 3848.5,-1064.34 h60
  text "TEXAS INSTRUMENTS" at 5113,-1064.34 h60
M12 Stackup:
  text ".Layer_Name" at 577,-858.49 h60
M13 Component Bodies Top:
  text ".Layer_Name" at 577,-858.49 h60
M14 Component Bodies Bottom:
  text ".Layer_Name" at 577,-858.49 h60
M15 Courtyards Top:
  text ".Layer_Name" at 577,-858.49 h60
M16 Courtyards Bottom:
  text ".Layer_Name" at 577,-858.49 h60
Drill Drawing:
  text ".Layer_Name" at 577,-858.49 h60

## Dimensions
0,0 to 7300,0 on M2 Board Dimensions
0,-400 to 1000,-400 on M2 Board Dimensions
7300,0 to 7300,1875 on M2 Board Dimensions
